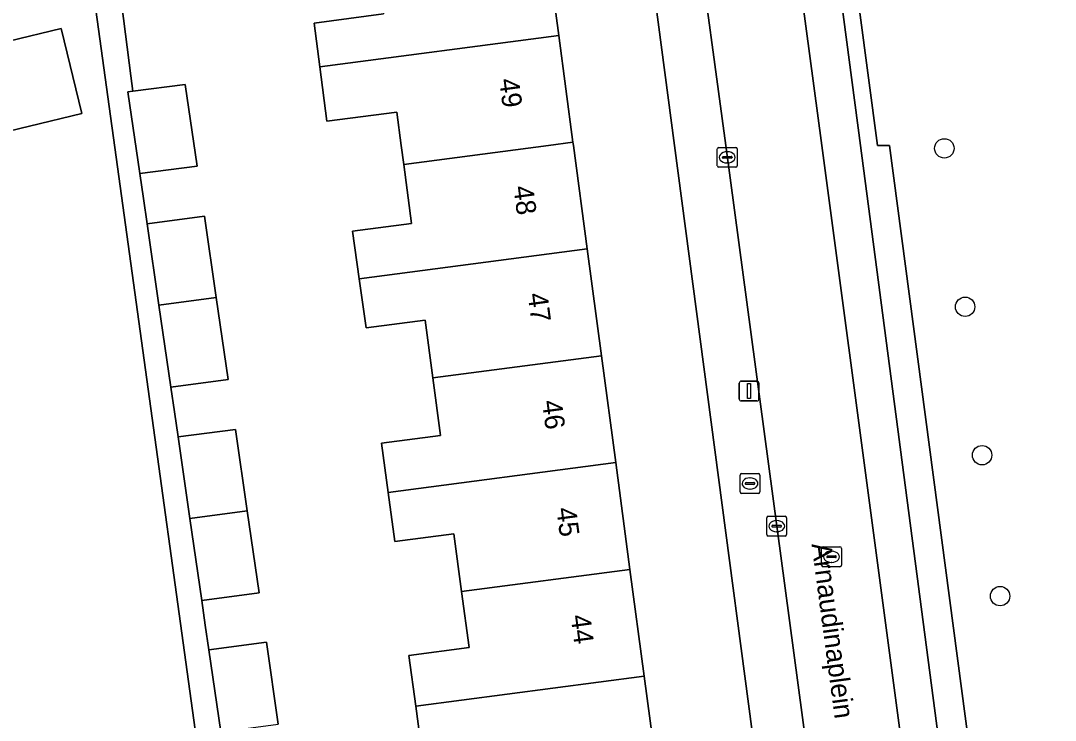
# Model space of a CAD drawing. Extents: x 163147 to 163550, y 380933 to 381639.
# Drawn here: x 163305.4 to 163357.6, y 381221 to 381256.3 of the extents above; entities that cross this region are included whole.
import ezdxf

# ---------------------------------------------------------------- set-up
doc = ezdxf.new("R2010")
doc.units = 0
for name, color, linetype in [('IMGEO_Boom', 7, 'Continuous'), ('IMGEO_Brandkraan', 7, 'Continuous'), ('IMGEO_Erf', 7, 'Continuous'), ('IMGEO_Groenvoorziening', 7, 'Continuous'), ('IMGEO_Kolk', 7, 'Continuous'), ('IMGEO_Lichtmast', 7, 'Continuous'), ('IMGEO_Openbare_ruimte_label', 7, 'Continuous'), ('IMGEO_Pand', 7, 'Continuous'), ('IMGEO_Pand_nummerreeks', 7, 'Continuous'), ('IMGEO_Parkeervlak_open', 7, 'Continuous'), ('IMGEO_Rijbaan_lokaal_open', 7, 'Continuous'), ('IMGEO_Rioolput', 7, 'Continuous'), ('IMGEO_Voetpad_open', 7, 'Continuous')]:
    doc.layers.add(name, color=color, linetype=linetype)

msp = doc.modelspace()

# ---------------------------------------------------------------- linework, layer by layer
at = {"layer": 'IMGEO_Boom'}
for centre in [(163351.99, 381249.851), (163353.04, 381241.864), (163353.894, 381234.382), (163354.802, 381227.274)]:
    msp.add_circle(centre, 0.489, dxfattribs=at)
at = {"layer": 'IMGEO_Brandkraan'}
for p, q in [((163341.689, 381232.529), (163341.689, 381233.381)), ((163341.764, 381233.455), (163342.616, 381233.455)), ((163342.177, 381233.235), (163342.202, 381233.235)), ((163342.69, 381233.381), (163342.69, 381232.529)), ((163341.948, 381232.949), (163341.948, 381232.961)), ((163342.386, 381232.912), (163341.988, 381232.912)), ((163341.991, 381232.998), (163342.389, 381232.998)), ((163342.2, 381232.675), (163342.175, 381232.675)), ((163342.432, 381232.961), (163342.432, 381232.949)), ((163342.616, 381232.455), (163341.764, 381232.455))]:
    msp.add_line(p, q, dxfattribs=at)
for points in [[(163341.689, 381232.529), (163341.689, 381233.381)], [(163341.764, 381233.455), (163342.616, 381233.455)], [(163342.69, 381233.381), (163342.69, 381232.529)], [(163342.616, 381232.455), (163341.764, 381232.455)]]:
    msp.add_lwpolyline(points, dxfattribs=at)
for centre, radius, start, end in [((163341.766, 381233.379), 0.0765, 91.552, 178.448), ((163341.766, 381233.379), 0.0765, 91.552, 178.448), ((163342.614, 381233.379), 0.0765, 1.552, 88.448), ((163342.614, 381233.379), 0.0765, 1.552, 88.448), ((163341.988, 381232.958), 0.0403, 85.8775, 175.7526), ((163341.985, 381232.948), 0.0366, 178.938, 274.7102), ((163342.389, 381232.955), 0.043, 264.8664, 352.4533), ((163342.393, 381232.96), 0.0386, 1.7309, 96.639), ((163341.766, 381232.531), 0.0765, 181.552, 268.448), ((163341.766, 381232.531), 0.0765, 181.552, 268.448), ((163342.614, 381232.531), 0.0765, 271.552, 358.448), ((163342.614, 381232.531), 0.0765, 271.552, 358.448)]:
    msp.add_arc(centre, radius, start, end, dxfattribs=at)
for centre, major_axis, ratio, start_param, end_param in [((163342.176, 381232.955), (-0.387, 0.002), 0.722429, 4.712389, 7.853982), ((163342.201, 381232.955), (-0.39, 0.002), 0.717154, 1.570796, 4.712389)]:
    msp.add_ellipse(centre, major_axis=major_axis, ratio=ratio, start_param=start_param, end_param=end_param, dxfattribs=at)
at = {"layer": 'IMGEO_Erf'}
for points in [[(163344.525, 381203.718), (163338.386, 381250), (163336.432, 381264.739)], [(163309.951, 381261.415), (163310.96, 381253.514), (163311.063, 381252.731), (163313.708, 381253.077), (163314.306, 381248.962), (163311.411, 381248.583), (163311.594, 381247.324), (163311.779, 381246.049), (163314.674, 381246.427), (163315.27, 381242.326), (163315.87, 381238.194), (163312.975, 381237.815), (163313.156, 381236.572), (163313.341, 381235.301), (163316.236, 381235.68), (163316.832, 381231.574), (163317.433, 381227.439), (163314.539, 381227.059), (163314.719, 381225.817), (163314.901, 381224.567), (163317.796, 381224.947), (163318.395, 381220.822)], [(163289.781, 381249.639), (163311.555, 381199.092), (163317.049, 381199.939), (163308.6, 381261.231), (163298.145, 381259.806)], [(163331.807, 381261.052), (163332.541, 381255.546), (163333.259, 381250.162), (163333.281, 381250), (163333.978, 381244.779), (163334.696, 381239.394), (163335.414, 381234.01), (163336.133, 381228.626), (163336.851, 381223.241), (163337.57, 381217.857)], [(163325.656, 381219.313), (163325.331, 381221.731), (163324.989, 381224.279), (163328.019, 381224.686), (163327.64, 381227.512), (163327.25, 381230.418), (163324.275, 381230.028), (163323.942, 381232.506), (163323.61, 381234.984), (163326.584, 381235.374), (163326.194, 381238.28), (163325.804, 381241.186), (163322.83, 381240.796), (163322.483, 381243.272), (163322.147, 381245.669), (163325.12, 381246.068), (163324.726, 381249.044), (163324.6, 381250), (163324.378, 381251.679), (163320.853, 381251.22), (163320.495, 381253.967), (163320.208, 381256.169), (163323.697, 381256.63)]]:
    msp.add_lwpolyline(points, dxfattribs=at)
msp.add_lwpolyline([(163307.445, 381255.9), (163308.483, 381251.605), (163297.911, 381249.049), (163296.872, 381253.344)], close=True, dxfattribs=at)
at = {"layer": 'IMGEO_Groenvoorziening'}
msp.add_lwpolyline([(163351.235, 381277.461), (163347.195, 381277.427), (163347.186, 381277.498), (163346.331, 381277.403), (163345.564, 381277.317), (163344.998, 381277.236), (163345.169, 381275.947), (163346.512, 381276.133), (163350.919, 381276.369), (163352.031, 381268.049), (163347.274, 381267.448), (163346.315, 381267.327), (163348.618, 381250), (163349.216, 381250), (163354.88, 381207.411), (163356.493, 381207.594), (163356.477, 381207.718), (163360.869, 381208.352)], dxfattribs=at)
at = {"layer": 'IMGEO_Kolk'}
for p, q in [((163340.541, 381248.973), (163340.541, 381249.825)), ((163340.616, 381249.899), (163341.468, 381249.899)), ((163341.542, 381249.825), (163341.542, 381248.973)), ((163340.8, 381249.393), (163340.8, 381249.405)), ((163341.238, 381249.356), (163340.84, 381249.356)), ((163340.843, 381249.442), (163341.241, 381249.442)), ((163341.029, 381249.679), (163341.054, 381249.679)), ((163341.284, 381249.405), (163341.284, 381249.393)), ((163341.468, 381248.899), (163340.616, 381248.899)), ((163341.052, 381249.119), (163341.027, 381249.119)), ((163343.036, 381230.377), (163343.036, 381231.229)), ((163343.111, 381231.303), (163343.963, 381231.303)), ((163343.524, 381231.083), (163343.549, 381231.083)), ((163344.037, 381231.229), (163344.037, 381230.377)), ((163343.295, 381230.797), (163343.295, 381230.809)), ((163343.733, 381230.76), (163343.335, 381230.76)), ((163343.338, 381230.846), (163343.736, 381230.846)), ((163343.547, 381230.523), (163343.522, 381230.523)), ((163343.779, 381230.809), (163343.779, 381230.797)), ((163343.963, 381230.303), (163343.111, 381230.303))]:
    msp.add_line(p, q, dxfattribs=at)
for points in [[(163340.541, 381248.973), (163340.541, 381249.825)], [(163340.616, 381249.899), (163341.468, 381249.899)], [(163341.542, 381249.825), (163341.542, 381248.973)], [(163341.468, 381248.899), (163340.616, 381248.899)], [(163343.036, 381230.377), (163343.036, 381231.229)], [(163343.111, 381231.303), (163343.963, 381231.303)], [(163344.037, 381231.229), (163344.037, 381230.377)], [(163343.963, 381230.303), (163343.111, 381230.303)]]:
    msp.add_lwpolyline(points, dxfattribs=at)
for centre, radius, start, end in [((163340.618, 381249.823), 0.0765, 91.552, 178.448), ((163340.618, 381249.823), 0.0765, 91.552, 178.448), ((163341.466, 381249.823), 0.0765, 1.552, 88.448), ((163341.466, 381249.823), 0.0765, 1.552, 88.448), ((163340.84, 381249.402), 0.0403, 85.8775, 175.7526), ((163340.837, 381249.392), 0.0366, 178.938, 274.7102), ((163341.241, 381249.399), 0.043, 264.8664, 352.4533), ((163341.245, 381249.404), 0.0386, 1.7309, 96.639), ((163340.618, 381248.975), 0.0765, 181.552, 268.448), ((163340.618, 381248.975), 0.0765, 181.552, 268.448), ((163341.466, 381248.975), 0.0765, 271.552, 358.448), ((163341.466, 381248.975), 0.0765, 271.552, 358.448), ((163343.113, 381231.227), 0.0765, 91.552, 178.448), ((163343.113, 381231.227), 0.0765, 91.552, 178.448), ((163343.961, 381231.227), 0.0765, 1.552, 88.448), ((163343.961, 381231.227), 0.0765, 1.552, 88.448), ((163343.335, 381230.806), 0.0403, 85.8775, 175.7526), ((163343.332, 381230.796), 0.0366, 178.938, 274.7102), ((163343.736, 381230.803), 0.043, 264.8664, 352.4533), ((163343.74, 381230.808), 0.0386, 1.7309, 96.639), ((163343.113, 381230.379), 0.0765, 181.552, 268.448), ((163343.113, 381230.379), 0.0765, 181.552, 268.448), ((163343.961, 381230.379), 0.0765, 271.552, 358.448), ((163343.961, 381230.379), 0.0765, 271.552, 358.448)]:
    msp.add_arc(centre, radius, start, end, dxfattribs=at)
for centre, major_axis, ratio, start_param, end_param in [((163341.028, 381249.399), (-0.387, 0.002), 0.722429, 4.712389, 7.853982), ((163341.053, 381249.399), (-0.39, 0.002), 0.717154, 1.570796, 4.712389), ((163343.523, 381230.803), (-0.387, 0.002), 0.722429, 4.712389, 7.853982), ((163343.548, 381230.803), (-0.39, 0.002), 0.717154, 1.570796, 4.712389)]:
    msp.add_ellipse(centre, major_axis=major_axis, ratio=ratio, start_param=start_param, end_param=end_param, dxfattribs=at)
at = {"layer": 'IMGEO_Lichtmast'}
for p, q in [((163341.649, 381237.214), (163341.649, 381238.014)), ((163341.649, 381238.014), (163341.649, 381237.214)), ((163341.749, 381238.114), (163342.539, 381238.114)), ((163342.539, 381238.114), (163341.749, 381238.114)), ((163342.639, 381238.014), (163342.639, 381237.214)), ((163342.639, 381237.214), (163342.639, 381238.014)), ((163342.539, 381237.114), (163341.749, 381237.114)), ((163341.749, 381237.114), (163342.539, 381237.114))]:
    msp.add_line(p, q, dxfattribs=at)
msp.add_lwpolyline([(163342.069, 381237.989), (163342.219, 381237.989), (163342.219, 381237.239), (163342.069, 381237.239), (163342.069, 381237.989)], dxfattribs=at)
for centre, start, end in [((163341.749, 381238.014), 90, 180), ((163341.749, 381238.014), 90, 180), ((163342.539, 381238.014), 0, 90), ((163342.539, 381238.014), 360, 90), ((163341.749, 381237.214), 180, 270), ((163341.749, 381237.214), 180, 270), ((163342.539, 381237.214), 270, 0), ((163342.539, 381237.214), 270, 0)]:
    msp.add_arc(centre, 0.1, start, end, dxfattribs=at)
at = {"layer": 'IMGEO_Pand'}
for points in [[(163331.807, 381261.052), (163323.263, 381259.924), (163323.279, 381259.799), (163323.697, 381256.63), (163320.208, 381256.169), (163320.495, 381253.967), (163332.541, 381255.546)], [(163308.483, 381251.605), (163307.445, 381255.9), (163296.872, 381253.344), (163297.911, 381249.049)], [(163332.541, 381255.546), (163320.495, 381253.967), (163320.853, 381251.22), (163324.378, 381251.679), (163324.6, 381250), (163324.726, 381249.044), (163332.023, 381250), (163333.259, 381250.162)], [(163311.063, 381252.731), (163310.813, 381252.698), (163311.411, 381248.583), (163314.306, 381248.962), (163313.708, 381253.077)], [(163322.483, 381243.272), (163333.978, 381244.779), (163333.281, 381250), (163333.259, 381250.162), (163332.023, 381250), (163324.726, 381249.044), (163325.12, 381246.068), (163322.147, 381245.669)], [(163311.779, 381246.049), (163312.375, 381241.947), (163315.27, 381242.326), (163314.674, 381246.427)], [(163334.696, 381239.394), (163333.978, 381244.779), (163322.483, 381243.272), (163322.83, 381240.796), (163325.804, 381241.186), (163326.194, 381238.28)], [(163315.27, 381242.326), (163312.375, 381241.947), (163312.975, 381237.815), (163315.87, 381238.194)], [(163334.696, 381239.394), (163326.194, 381238.28), (163326.584, 381235.374), (163323.61, 381234.984), (163323.942, 381232.506), (163335.414, 381234.01)], [(163313.341, 381235.301), (163313.938, 381231.194), (163316.832, 381231.574), (163316.236, 381235.68)], [(163335.414, 381234.01), (163323.942, 381232.506), (163324.275, 381230.028), (163327.25, 381230.418), (163327.64, 381227.512), (163336.133, 381228.626)], [(163316.832, 381231.574), (163313.938, 381231.194), (163314.539, 381227.059), (163317.433, 381227.439)], [(163336.133, 381228.626), (163327.64, 381227.512), (163328.019, 381224.686), (163324.989, 381224.279), (163325.331, 381221.731), (163336.851, 381223.241)], [(163314.901, 381224.567), (163315.5, 381220.442), (163318.395, 381220.822), (163317.796, 381224.947)], [(163337.57, 381217.857), (163336.851, 381223.241), (163325.331, 381221.731), (163325.656, 381219.313), (163328.629, 381219.713), (163329.028, 381216.737)]]:
    msp.add_lwpolyline(points, close=True, dxfattribs=at)
at = {"layer": 'IMGEO_Parkeervlak_open'}
for points in [[(163342.206, 381276.834), (163345.815, 381250), (163351.194, 381209.677)], [(163352.645, 381212.946), (163347.758, 381250), (163344.608, 381273.886)]]:
    msp.add_lwpolyline(points, dxfattribs=at)
at = {"layer": 'IMGEO_Rijbaan_lokaal_open'}
msp.add_lwpolyline([(163346.547, 381208.369), (163351.285, 381208.996), (163351.194, 381209.677), (163345.815, 381250), (163342.206, 381276.834), (163342.115, 381277.506), (163337.322, 381276.844), (163338.924, 381265.031), (163339.435, 381261.265), (163340.962, 381250)], close=True, dxfattribs=at)
at = {"layer": 'IMGEO_Rioolput'}
for p, q in [((163345.8, 381228.832), (163345.8, 381229.684)), ((163345.875, 381229.758), (163346.727, 381229.758)), ((163346.288, 381229.538), (163346.313, 381229.538)), ((163346.801, 381229.684), (163346.801, 381228.832)), ((163346.059, 381229.252), (163346.059, 381229.264)), ((163346.497, 381229.215), (163346.099, 381229.215)), ((163346.102, 381229.301), (163346.5, 381229.301)), ((163346.311, 381228.978), (163346.286, 381228.978)), ((163346.543, 381229.264), (163346.543, 381229.252)), ((163346.727, 381228.758), (163345.875, 381228.758))]:
    msp.add_line(p, q, dxfattribs=at)
for points in [[(163345.8, 381228.832), (163345.8, 381229.684)], [(163345.875, 381229.758), (163346.727, 381229.758)], [(163346.801, 381229.684), (163346.801, 381228.832)], [(163346.727, 381228.758), (163345.875, 381228.758)]]:
    msp.add_lwpolyline(points, dxfattribs=at)
for centre, radius, start, end in [((163345.877, 381229.682), 0.0765, 91.552, 178.448), ((163345.877, 381229.682), 0.0765, 91.552, 178.448), ((163346.725, 381229.682), 0.0765, 1.552, 88.448), ((163346.725, 381229.682), 0.0765, 1.552, 88.448), ((163346.099, 381229.261), 0.0403, 85.8775, 175.7526), ((163346.096, 381229.251), 0.0366, 178.938, 274.7102), ((163346.5, 381229.258), 0.043, 264.8664, 352.4533), ((163346.504, 381229.263), 0.0386, 1.7309, 96.639), ((163345.877, 381228.834), 0.0765, 181.552, 268.448), ((163345.877, 381228.834), 0.0765, 181.552, 268.448), ((163346.725, 381228.834), 0.0765, 271.552, 358.448), ((163346.725, 381228.834), 0.0765, 271.552, 358.448)]:
    msp.add_arc(centre, radius, start, end, dxfattribs=at)
for centre, major_axis, ratio, start_param, end_param in [((163346.287, 381229.258), (-0.387, 0.002), 0.722429, 4.712389, 7.853982), ((163346.312, 381229.258), (-0.39, 0.002), 0.717154, 1.570796, 4.712389)]:
    msp.add_ellipse(centre, major_axis=major_axis, ratio=ratio, start_param=start_param, end_param=end_param, dxfattribs=at)
at = {"layer": 'IMGEO_Voetpad_open'}
for points in [[(163333.923, 381291.813), (163330.728, 381291.79), (163331.089, 381289.4), (163333.107, 381289.679), (163334.924, 381276.051), (163335.797, 381269.508), (163336.166, 381266.742), (163336.175, 381266.672), (163336.432, 381264.739), (163338.386, 381250), (163344.525, 381203.718), (163344.714, 381202.289), (163345.388, 381197.208), (163345.403, 381197.095), (163346.101, 381192.014), (163346.127, 381191.825), (163347.476, 381182.004), (163347.497, 381181.851), (163348.195, 381176.771), (163348.228, 381176.531), (163348.863, 381171.54), (163349.084, 381169.804), (163349.596, 381165.787)], [(163359.819, 381167.91), (163359.554, 381172.345), (163359.283, 381174.378), (163355.89, 381199.858), (163355.721, 381201.083), (163355.113, 381205.656), (163354.88, 381207.411), (163349.216, 381250), (163348.618, 381250), (163346.315, 381267.327), (163346.203, 381268.173), (163345.209, 381275.649), (163345.169, 381275.947), (163344.998, 381277.236), (163345.564, 381277.317), (163345.341, 381279.02), (163343.681, 381291.676)], [(163340.962, 381250), (163339.435, 381261.265), (163338.924, 381265.031), (163337.322, 381276.844), (163336.946, 381279.618), (163335.771, 381288.284)], [(163344.608, 381273.886), (163347.758, 381250), (163352.645, 381212.946)], [(163315.5, 381220.442), (163314.901, 381224.567), (163314.719, 381225.817), (163314.539, 381227.059), (163313.938, 381231.194), (163313.341, 381235.301), (163313.156, 381236.572), (163312.975, 381237.815), (163312.375, 381241.947), (163311.779, 381246.049), (163311.594, 381247.324), (163311.411, 381248.583), (163310.813, 381252.698), (163311.063, 381252.731), (163310.96, 381253.514), (163309.951, 381261.415)], [(163298.145, 381259.806), (163308.6, 381261.231), (163317.049, 381199.939), (163311.555, 381199.092), (163289.781, 381249.639)], [(163352.057, 381166.362), (163349.28, 381187.853), (163347.154, 381203.779), (163346.697, 381207.275), (163346.547, 381208.369), (163340.962, 381250)]]:
    msp.add_lwpolyline(points, dxfattribs=at)

# ---------------------------------------------------------------- texts
at = {"layer": 'IMGEO_Openbare_ruimte_label'}
msp.add_text('Arnaudinaplein', height=1, rotation=277.5871, dxfattribs=at).set_placement((163345.29, 381229.898))
at = {"layer": 'IMGEO_Pand_nummerreeks'}
for s, p in [('49', (163329.529, 381253.325)), ('48', (163330.25, 381247.914)), ('47', (163330.972, 381242.509)), ('46', (163331.693, 381237.101)), ('45', (163332.415, 381231.693)), ('44', (163333.136, 381226.285))]:
    msp.add_text(s, height=1, rotation=277.5992, dxfattribs=at).set_placement(p)

doc.saveas('drawing.dxf')
